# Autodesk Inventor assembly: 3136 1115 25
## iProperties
Shininess: 0.0
Length Units: 11269
Angle Units: 11279
Time Units: 11290
Mass Units: 11283
Length Display Precision: 3
Angle Display Precision: 2
Compacted: True
Created: 2000-11
Part Number: 3136 1115 25
Description: Cable conductor
Document SubType Name: Assembly
Designer: Joe M
Engineer: Joe M
Density: 0.0
Volumn: 0.0
Area: 0.0
PropertySet Name: Model Information
Control State: 0
Master: False
Checked Out: False
Last Check In By: brjdn
Last Check In Date: 2002-03-12
Title: Kabelledare vridbar
Author: Joe M
